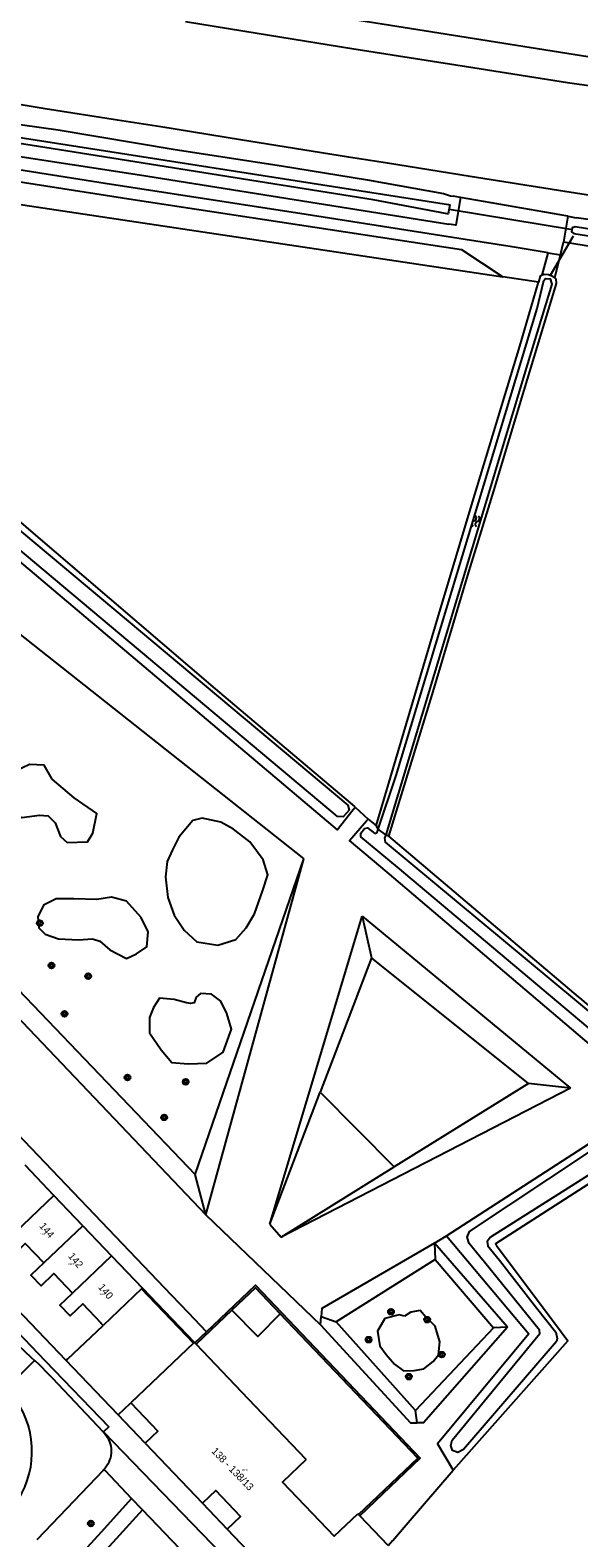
# Model space of a CAD drawing. Extents: x 132994 to 136000, y 393499 to 395512.
# Drawn here: x 133310.5 to 133385.4, y 394045 to 394251.1 of the extents above; entities that cross this region are included whole.
import ezdxf

# ---------------------------------------------------------------- set-up
doc = ezdxf.new("R2010")
doc.units = 0
for name, color, linetype in [('gg-anno-huisnummerreeks BGT', 7, 'Continuous'), ('gg-knt-bronhoudergrens', 7, 'Continuous'), ('gg-kntw-bovenkant insteek waterloop', 7, 'Continuous'), ('gg-kwrk-duiker nz buis', 7, 'Continuous'), ('gg-kwrk-kunstwerk niveau 01', 7, 'Continuous'), ('gt-grn-groengrens', 7, 'Continuous'), ('gt-symb-boom', 7, 'Continuous'), ('gt-symb-watersymbool', 7, 'Continuous'), ('gx-grn-maaiveld', 7, 'Continuous'), ('kenmerkpunt-x pandkandidaat', 7, 'Continuous')]:
    doc.layers.add(name, color=color, linetype=linetype)

# ---------------------------------------------------------------- blocks, each defined once
blk = doc.blocks.new('gt0-WA')
at = {"layer": 'gt-symb-watersymbool'}
for centre, start, end in [((-0.32, 0.02), 28.0725, 151.9275), ((0.43, 0.42), 208.0725, 331.9275), ((-0.32, -0.43), 28.0725, 151.9275), ((0.43, -0.03), 208.0725, 331.9275)]:
    blk.add_arc(centre, 0.425, start, end, dxfattribs=at)
blk = doc.blocks.new('gt0-BOOM')
at = {"layer": 'gt-symb-boom'}
for radius in [0.4, 0.2]:
    blk.add_circle((0, 0), radius, dxfattribs=at)

msp = doc.modelspace()

# ---------------------------------------------------------------- linework, layer by layer
at = {"layer": 'gg-knt-bronhoudergrens'}
msp.add_line((133245.44, 394236.82), (133375.05, 394217.4), dxfattribs=at)
at = {"layer": 'gg-kntw-bovenkant insteek waterloop'}
for p in [(133383.89, 394225.66), (133449.24, 394211.39)]:
    msp.add_line(p, (133383.33, 394222.11), dxfattribs=at)
msp.add_lwpolyline([(133235.77, 394245.07), (133325.43, 394231.31), (133367.65, 394224.61)], dxfattribs=at)
at = {"layer": 'gg-kwrk-duiker nz buis'}
for p, q in [((133367.7, 394226.63), (133384.53, 394223.84)), ((133384.64, 394222.94), (133381.51, 394217.58))]:
    msp.add_line(p, q, dxfattribs=at)
at = {"layer": 'gg-kwrk-kunstwerk niveau 01'}
for points in [[(133344.62, 394075.67), (133341.25, 394079.21), (133338.04, 394076.16)], [(133344.62, 394075.67), (133341.56, 394072.57), (133338.04, 394076.16)]]:
    msp.add_lwpolyline(points, dxfattribs=at)
at = {"layer": 'gt-grn-groengrens'}
for p, q in [((133382.9, 394220.41), (133383.33, 394222.11)), ((133381.22, 394220.68), (133382.9, 394220.41))]:
    msp.add_line(p, q, dxfattribs=at)
for points in [[(133381.22, 394220.68), (133376.32, 394221.47), (133372.2, 394222.14), (133348.15, 394225.9), (133320.7, 394230.16), (133289.89, 394235.04), (133256.76, 394240.15), (133238.35, 394242.87)], [(133240.4, 394241.12), (133324.55, 394227.97), (133369.39, 394221.13), (133375.05, 394217.4)]]:
    msp.add_lwpolyline(points, dxfattribs=at)
at = {"layer": 'gx-grn-maaiveld'}
for p, q in [((133369.27, 394228.23), (133368.26, 394228.41)), ((133383.89, 394225.66), (133369.27, 394228.23)), ((133383.89, 394225.66), (133385.05, 394225.47)), ((133382.11, 394217.25), (133382.9, 394220.41)), ((133379.89, 394216.68), (133375.05, 394217.4)), ((133301.57, 394174.46), (133347.86, 394137.85)), ((133258.59, 394168.91), (133334.45, 394089.2)), ((133262.83, 394168.02), (133333.02, 394094.71)), ((133354.87, 394144.91), (133354.76, 394145)), ((133354.87, 394144.91), (133356.66, 394143.29)), ((133356.66, 394143.29), (133357.54, 394142.55)), ((133357.74, 394142.38), (133357.99, 394141.91)), ((133359.04, 394141.13), (133357.99, 394141.91)), ((133359.43, 394140.94), (133359.04, 394141.13)), ((133333.02, 394094.71), (133347.86, 394137.85)), ((133334.45, 394089.2), (133347.86, 394137.85)), ((133343.2, 394087.9), (133355.84, 394130.01)), ((133355.84, 394130.01), (133357.1, 394124.33)), ((133355.84, 394130.01), (133384.27, 394106.49)), ((133357.1, 394124.33), (133350.1, 394105.98)), ((133378.54, 394107.15), (133357.1, 394124.33)), ((133329.81, 394078.18), (133303.52, 394105.74)), ((133343.2, 394087.9), (133350.1, 394105.98)), ((133384.27, 394106.49), (133344.78, 394086.16)), ((133350.1, 394105.98), (133360.18, 394095.74)), ((133378.54, 394107.15), (133360.18, 394095.74)), ((133384.27, 394106.49), (133378.54, 394107.15)), ((133313.72, 394091.84), (133309.78, 394095.96)), ((133344.78, 394086.16), (133360.18, 394095.74)), ((133315.35, 394069.33), (133291.61, 394094.2)), ((133334.45, 394089.2), (133333.02, 394094.71)), ((133313.72, 394091.84), (133308.39, 394086.75)), ((133317.66, 394087.71), (133313.72, 394091.84)), ((133334.45, 394089.2), (133350.12, 394074.17)), ((133317.66, 394087.71), (133312.33, 394082.62)), ((133317.66, 394087.71), (133321.59, 394083.59)), ((133343.2, 394087.9), (133344.78, 394086.16)), ((133365.72, 394085.3), (133367.34, 394086.31)), ((133365.72, 394085.3), (133365.8, 394083.1)), ((133375.67, 394073.82), (133365.72, 394085.3)), ((133321.59, 394083.59), (133316.27, 394078.51)), ((133321.59, 394083.59), (133325.8, 394079.18)), ((133365.8, 394083.1), (133352.29, 394074.58)), ((133365.8, 394083.1), (133373.75, 394073.75)), ((133325.69, 394079.08), (133320.43, 394074.06)), ((133325.8, 394079.18), (133325.69, 394079.08)), ((133332.78, 394071.66), (133325.69, 394079.08)), ((133325.8, 394079.18), (133332.89, 394071.77)), ((133332.11, 394075.78), (133329.81, 394078.18)), ((133334.56, 394073.2), (133332.11, 394075.78)), ((133338.04, 394076.16), (133333.14, 394071.5)), ((133350.12, 394074.17), (133350.23, 394075.28)), ((133350.23, 394075.28), (133352.29, 394074.58)), ((133334.56, 394073.2), (133332.97, 394071.68)), ((133363.12, 394062.44), (133352.29, 394074.58)), ((133373.75, 394073.75), (133363.12, 394062.44)), ((133375.67, 394073.82), (133373.75, 394073.75)), ((133332.78, 394071.66), (133324.22, 394063.49)), ((133332.89, 394071.77), (133332.78, 394071.66)), ((133332.89, 394071.77), (133332.97, 394071.68)), ((133332.97, 394071.68), (133333.14, 394071.5)), ((133307.19, 394065.44), (133311.08, 394069.3)), ((133322.5, 394061.85), (133315.35, 394069.33)), ((133322.5, 394061.85), (133324.22, 394063.49)), ((133363.32, 394060.77), (133363.12, 394062.44)), ((133326.18, 394058), (133322.5, 394061.85)), ((133320.5, 394059.54), (133320.47, 394059.51)), ((133326.18, 394058), (133334.03, 394049.78)), ((133339.64, 394034.45), (133325.82, 394048.88)), ((133334.03, 394049.78), (133337.4, 394046.24)), ((133355.32, 394048.22), (133355.21, 394048.34)), ((133355.49, 394048.04), (133355.32, 394048.22)), ((133359.36, 394043.98), (133355.49, 394048.04)), ((133337.4, 394046.24), (133345.2, 394038.08))]:
    msp.add_line(p, q, dxfattribs=at)
for points in [[(133477.26, 394233.07), (133471.9, 394233.95), (133442.5, 394238.64), (133411.76, 394243.56), (133389.51, 394247.02), (133358.56, 394251.91), (133333.03, 394255.99), (133297.86, 394261.6), (133274.58, 394265.33), (133243.64, 394270.28), (133214.41, 394274.9), (133182.69, 394280.01), (133151.95, 394284.94), (133119.95, 394290.05), (133101.68, 394293.04)], [(133000, 394283.61), (133006.65, 394282.79), (133009.42, 394282.22), (133051.12, 394276.6), (133083.16, 394271.78), (133137.1, 394263.26), (133176.74, 394257.15), (133239.73, 394247.29), (133319.89, 394234.75), (133367.61, 394227.28), (133367.8, 394227.24), (133367.58, 394225.98), (133367.42, 394226.01), (133357.3, 394227.92), (133315.33, 394234.59), (133277.4, 394240.61), (133240.55, 394246.47), (133201.95, 394252.14), (133139.43, 394262.02), (133051.35, 394275.59), (133009.25, 394281.47), (133006.61, 394281.68), (133000, 394282.47)], [(133098.44, 394271.62), (133113.79, 394269.24), (133135.01, 394266.02), (133154.52, 394262.95), (133175.04, 394259.64), (133230.39, 394250.78), (133249.11, 394247.87), (133285.7, 394242.17), (133296.88, 394240.16), (133304.19, 394238.9), (133314.3, 394237.48), (133330.27, 394234.8), (133344.79, 394232.54), (133356.53, 394230.63), (133366.93, 394228.78), (133367.87, 394228.47), (133368.26, 394228.41)], [(133331.67, 394252.31), (133341.5, 394250.71), (133354.41, 394248.61), (133370.92, 394246.01), (133383.84, 394243.95), (133387.43, 394243.45), (133399.14, 394241.6), (133408.35, 394240.05), (133418.6, 394238.43), (133429.66, 394236.66), (133446.13, 394234.1), (133458.56, 394232.05), (133469.68, 394230.32), (133476.69, 394229.21)], [(133474.72, 394214.61), (133474.58, 394214.64), (133459.14, 394216.98), (133449.06, 394218.62), (133440.24, 394220.04), (133432.66, 394221.32), (133426.05, 394222.31), (133416.08, 394223.9), (133405.05, 394225.67), (133396.93, 394226.98), (133383.5, 394229.04), (133370.57, 394231.1), (133359.29, 394232.91), (133353.97, 394233.74), (133339.19, 394236.13), (133328.31, 394237.88), (133322.4, 394238.81), (133312.52, 394240.37), (133303.25, 394241.89), (133291.56, 394243.8), (133281.21, 394245.47), (133268.92, 394247.41), (133255.61, 394249.52), (133245.86, 394251.11)], [(133226.43, 394246.51), (133229, 394244.43), (133229.08, 394244.36), (133265.07, 394215.25), (133306.28, 394180.76), (133352.39, 394141.8), (133354.6, 394144.57), (133354.68, 394144.68), (133354.87, 394144.91)], [(133233.58, 394245.41), (133236.03, 394243.38), (133247.17, 394234.15), (133309.55, 394182.31), (133353.84, 394145.2), (133354.03, 394144.51), (133353.24, 394143.57), (133352.46, 394143.64), (133308.58, 394180.49), (133245.9, 394232.5), (133232.4, 394243.92), (133229.99, 394245.96)], [(133248.54, 394234.22), (133268.55, 394217.53), (133281.76, 394206.59), (133307.5, 394185.26), (133310.58, 394182.62), (133335.76, 394161.06), (133354.76, 394145)], [(133369.27, 394228.23), (133368.61, 394224.44), (133367.65, 394224.61)], [(133395.46, 394223.71), (133387.35, 394225.14), (133385.05, 394225.47)], [(133449.83, 394213.82), (133448.61, 394214.01), (133423.17, 394218.09), (133384.92, 394224.22), (133384.51, 394224.09), (133384.43, 394223.54), (133384.72, 394223.31), (133411.05, 394219.17), (133449.77, 394212.88)], [(133380.42, 394217.62), (133381.21, 394220.64), (133381.22, 394220.68)], [(133357.99, 394141.91), (133360.44, 394149.23), (133366.61, 394169.6), (133379.74, 394213.06), (133380.63, 394216.9), (133380.86, 394217.16), (133381.48, 394217.13), (133381.71, 394216.41), (133378.39, 394205.51), (133368.88, 394173.83), (133359.04, 394141.13)], [(133382.11, 394217.25), (133382.29, 394217.11), (133382.33, 394216.49), (133377.89, 394201.88), (133373.76, 394188.13), (133370.21, 394176.61), (133365.32, 394160.26), (133359.43, 394140.94)], [(133380.42, 394217.62), (133380.13, 394217.5), (133379.89, 394216.68)], [(133382.11, 394217.25), (133381.87, 394217.44), (133381.27, 394217.67), (133380.68, 394217.73), (133380.42, 394217.62)], [(133357.74, 394142.38), (133360.79, 394152.65), (133366.14, 394170.77), (133370.74, 394186.13), (133377.37, 394207.92), (133379.89, 394216.68)], [(133313.49, 394148.74), (133312.38, 394150.65), (133310.4, 394150.73), (133308.49, 394149.85), (133306.43, 394148.35), (133306.03, 394146.84), (133306.74, 394144.54), (133309.36, 394143.5), (133311.74, 394143.82), (133312.94, 394143.74), (133313.89, 394142.79), (133314.6, 394140.88), (133315.55, 394140.09), (133318.33, 394140.17), (133319.05, 394141.36), (133319.6, 394144.06), (133316.51, 394146.2), (133313.49, 394148.74)], [(133341.11, 394130.33), (133342.23, 394133.42), (133342.94, 394135.65), (133342.3, 394137.71), (133340.48, 394140.17), (133338.26, 394141.92), (133336.51, 394142.87), (133333.97, 394143.42), (133332.7, 394143.11), (133330.8, 394140.8), (133329.92, 394139.06), (133329.21, 394137.47), (133328.97, 394135.41), (133329.29, 394132.55), (133330.16, 394130.17), (133331.51, 394128.1), (133333.26, 394126.52), (133336.11, 394126.04), (133338.57, 394126.83), (133340, 394128.42), (133341.11, 394130.33)], [(133367.34, 394086.31), (133395.93, 394104.82), (133359.22, 394136.03), (133354.1, 394140.35), (133356.42, 394143.02), (133356.52, 394143.13), (133356.66, 394143.29)], [(133397.56, 394105.66), (133360.63, 394136.72), (133355.66, 394140.86), (133355.63, 394141.34), (133356.14, 394142), (133356.55, 394142.1), (133357.55, 394141.29), (133357.88, 394141.46), (133357.99, 394141.91), (133357.99, 394141.91)], [(133357.74, 394142.38), (133357.68, 394142.43), (133357.54, 394142.55)], [(133359.04, 394141.13), (133359.01, 394141.05), (133358.89, 394140.66), (133358.98, 394140.12), (133401.24, 394104.94)], [(133359.43, 394140.94), (133385.33, 394118.98), (133385.48, 394118.85), (133385.49, 394118.84), (133385.51, 394118.83), (133403.09, 394103.92), (133374.02, 394085.21), (133374.13, 394085.06), (133374.16, 394085.01), (133378.1, 394079.76), (133382.2, 394074.27), (133383.91, 394071.98), (133368.23, 394054.3)], [(133316.43, 394132.39), (133314.05, 394132.39), (133312.3, 394131.52), (133311.51, 394129.93), (133311.67, 394128.42), (133312.54, 394127.55), (133314.36, 394126.91), (133317.06, 394126.76), (133318.97, 394126.91), (133320, 394126.6), (133321.35, 394125.41), (133323.65, 394124.22), (133325, 394124.85), (133326.43, 394125.8), (133326.59, 394127.87), (133325.64, 394129.85), (133323.65, 394132.07), (133321.59, 394132.63), (133319.6, 394132.31), (133316.43, 394132.39)], [(133333.76, 394119.45), (133333.14, 394118.96), (133332.86, 394118.16), (133332.39, 394118.08), (133331.85, 394118.18), (133330.16, 394118.61), (133328.15, 394118.82), (133327.3, 394117.55), (133326.77, 394116.17), (133326.77, 394114.05), (133328.36, 394111.73), (133329.84, 394110.03), (133332.07, 394109.82), (133334.61, 394109.93), (133336.83, 394111.41), (133337.99, 394114.58), (133337.36, 394116.7), (133336.51, 394118.39), (133335.24, 394119.35), (133333.76, 394119.45)], [(133401.19, 394103.79), (133373.34, 394086.16), (133372.91, 394085.54), (133372.98, 394084.97), (133373.35, 394084.5), (133374.56, 394082.99), (133379.64, 394076.5), (133382.26, 394073.16), (133382.46, 394072.29), (133382.34, 394071.87), (133369.64, 394057.14), (133368.89, 394056.73), (133368.15, 394056.97), (133367.91, 394057.67), (133368.13, 394058.41), (133380.07, 394072.97), (133380.02, 394073.41), (133372.51, 394082.72), (133371.84, 394083.55), (133370.44, 394085.27), (133370.17, 394086.16), (133370.46, 394086.91), (133397.57, 394104.9)], [(133308.39, 394086.75), (133306.65, 394085.08), (133308.05, 394083.61), (133309.79, 394085.28), (133312.33, 394082.62)], [(133365.72, 394085.3), (133350.33, 394076.38), (133350.23, 394075.28)], [(133367.34, 394086.31), (133378.59, 394072.91), (133366.11, 394057.88), (133368.23, 394054.3)], [(133312.33, 394082.62), (133310.59, 394080.96), (133311.99, 394079.49), (133313.73, 394081.16), (133316.27, 394078.51)], [(133334.56, 394073.2), (133341.26, 394079.56), (133363.76, 394055.92), (133355.49, 394048.04)], [(133302.74, 394077.14), (133303.89, 394078.28), (133312.51, 394069.26), (133321.21, 394060.2), (133320.5, 394059.54)], [(133311.08, 394069.3), (133310.67, 394069.67), (133302.74, 394077.14)], [(133320.43, 394074.06), (133320.14, 394074.37), (133320.19, 394074.41), (133317.67, 394077.05), (133315.92, 394075.38), (133314.52, 394076.84), (133316.27, 394078.51)], [(133355.32, 394048.22), (133363.41, 394055.93), (133344.62, 394075.67)], [(133361.61, 394075.35), (133360.88, 394075.54), (133358.9, 394075.01), (133357.9, 394073.29), (133358.23, 394071.31), (133359.09, 394070.12), (133360.22, 394068.8), (133361.48, 394067.87), (133362.93, 394067.94), (133364.25, 394068.14), (133365.51, 394069.13), (133366.24, 394070.05), (133366.44, 394071.84), (133365.77, 394073.96), (133364.52, 394075.21), (133363.72, 394076.14), (133362.47, 394075.87), (133361.61, 394075.35)], [(133315.35, 394069.33), (133315.57, 394069.49), (133320.43, 394074.06)], [(133350.12, 394074.17), (133362.44, 394060.77), (133363.32, 394060.77)], [(133375.67, 394073.82), (133364.2, 394060.78), (133363.32, 394060.77)], [(133348.16, 394055.74), (133340.31, 394063.98), (133333.14, 394071.5)], [(133311.08, 394069.3), (133311.16, 394069.23), (133311.64, 394068.77), (133312.11, 394068.31), (133312.58, 394067.84), (133313.05, 394067.36), (133313.51, 394066.88), (133320.41, 394059.57), (133320.44, 394059.54), (133320.47, 394059.51)], [(133250.63, 393988.69), (133291.47, 394031.81), (133294.54, 394034.96), (133307.69, 394048.84), (133308.29, 394049.56), (133308.84, 394050.33), (133309.32, 394051.14), (133309.73, 394051.99), (133310.08, 394052.87), (133310.35, 394053.78), (133310.55, 394054.7), (133310.67, 394055.64), (133310.72, 394056.59), (133310.69, 394057.53), (133310.61, 394058.48), (133310.46, 394059.42), (133310.23, 394060.34), (133309.93, 394061.24), (133309.56, 394062.12), (133309.12, 394062.95), (133308.77, 394063.51)], [(133324.22, 394063.49), (133327.9, 394059.64), (133326.18, 394058)], [(133320.47, 394059.51), (133320.68, 394059.28), (133320.87, 394059.03), (133321.04, 394058.76), (133321.19, 394058.48), (133321.31, 394058.19), (133321.41, 394057.89), (133321.48, 394057.58), (133321.52, 394057.26), (133321.54, 394056.95), (133321.53, 394056.63), (133321.49, 394056.31), (133321.43, 394055.99), (133321.33, 394055.69), (133321.22, 394055.39), (133321.07, 394055.1), (133320.91, 394054.83), (133320.72, 394054.57), (133320.51, 394054.34)], [(133320.5, 394059.54), (133344.68, 394034.53), (133347.98, 394031.93)], [(133311.45, 394044.82), (133311.48, 394044.85), (133320.49, 394054.31), (133320.5, 394054.33), (133320.51, 394054.34)], [(133320.51, 394054.34), (133320.52, 394054.34), (133320.53, 394054.35), (133320.54, 394054.35), (133320.55, 394054.35), (133320.56, 394054.36), (133320.57, 394054.36), (133320.58, 394054.36), (133320.59, 394054.36), (133320.6, 394054.35), (133320.61, 394054.35), (133320.62, 394054.34), (133320.63, 394054.34), (133320.64, 394054.33), (133320.65, 394054.32), (133320.66, 394054.31), (133320.67, 394054.3), (133324.34, 394050.43)], [(133348.16, 394055.74), (133344.94, 394052.68), (133351.99, 394045.28), (133355.21, 394048.34)], [(133359.39, 394044), (133359.97, 394044.67), (133359.99, 394044.69), (133361.81, 394046.82), (133368.23, 394054.3)], [(133324.34, 394050.43), (133320.19, 394045.84), (133298.11, 394021.7)], [(133325.82, 394048.88), (133325.81, 394048.89), (133324.34, 394050.43)], [(133337.4, 394046.24), (133339.22, 394047.97), (133335.84, 394051.51), (133334.03, 394049.78)], [(133325.82, 394048.88), (133321.76, 394044.41), (133318.2, 394040.52)]]:
    msp.add_lwpolyline(points, dxfattribs=at)

# ---------------------------------------------------------------- block references
at = {"layer": 'gt-symb-boom'}
for p in [(133311.79, 394129.07), (133313.4, 394123.27), (133318.4, 394121.82), (133315.18, 394116.66), (133323.77, 394107.96), (133331.72, 394107.37), (133328.79, 394102.51), (133359.76, 394075.95), (133364.7, 394074.87), (133356.7, 394072.13), (133366.69, 394070.09), (133362.18, 394067.08), (133318.76, 394047.01)]:
    msp.add_blockref('gt0-BOOM', p, dxfattribs=at)
at = {"layer": 'gt-symb-watersymbool', "rotation": -101.13011108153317}
msp.add_blockref('gt0-WA', (133371.35, 394184.04), dxfattribs=at)

# ---------------------------------------------------------------- texts
at = {"layer": 'gg-anno-huisnummerreeks BGT'}
for s, rotation, p in [('144', 310, (133311.67, 394087.63)), ('142', 310, (133315.61, 394083.51)), ('140', 310, (133319.71, 394079.27)), ('138 - 138/13', 314, (133335.17, 394056.82))]:
    msp.add_text(s, height=1, rotation=rotation, dxfattribs=at).set_placement(p)
at = {"layer": 'kenmerkpunt-x pandkandidaat'}
for p in [(133311.78, 394086.48), (133315.72, 394082.36), (133319.79, 394078.23), (133339.45, 394054.21)]:
    msp.add_text('PNDK', height=0.2, dxfattribs=at).set_placement(p)

doc.saveas('drawing.dxf')
